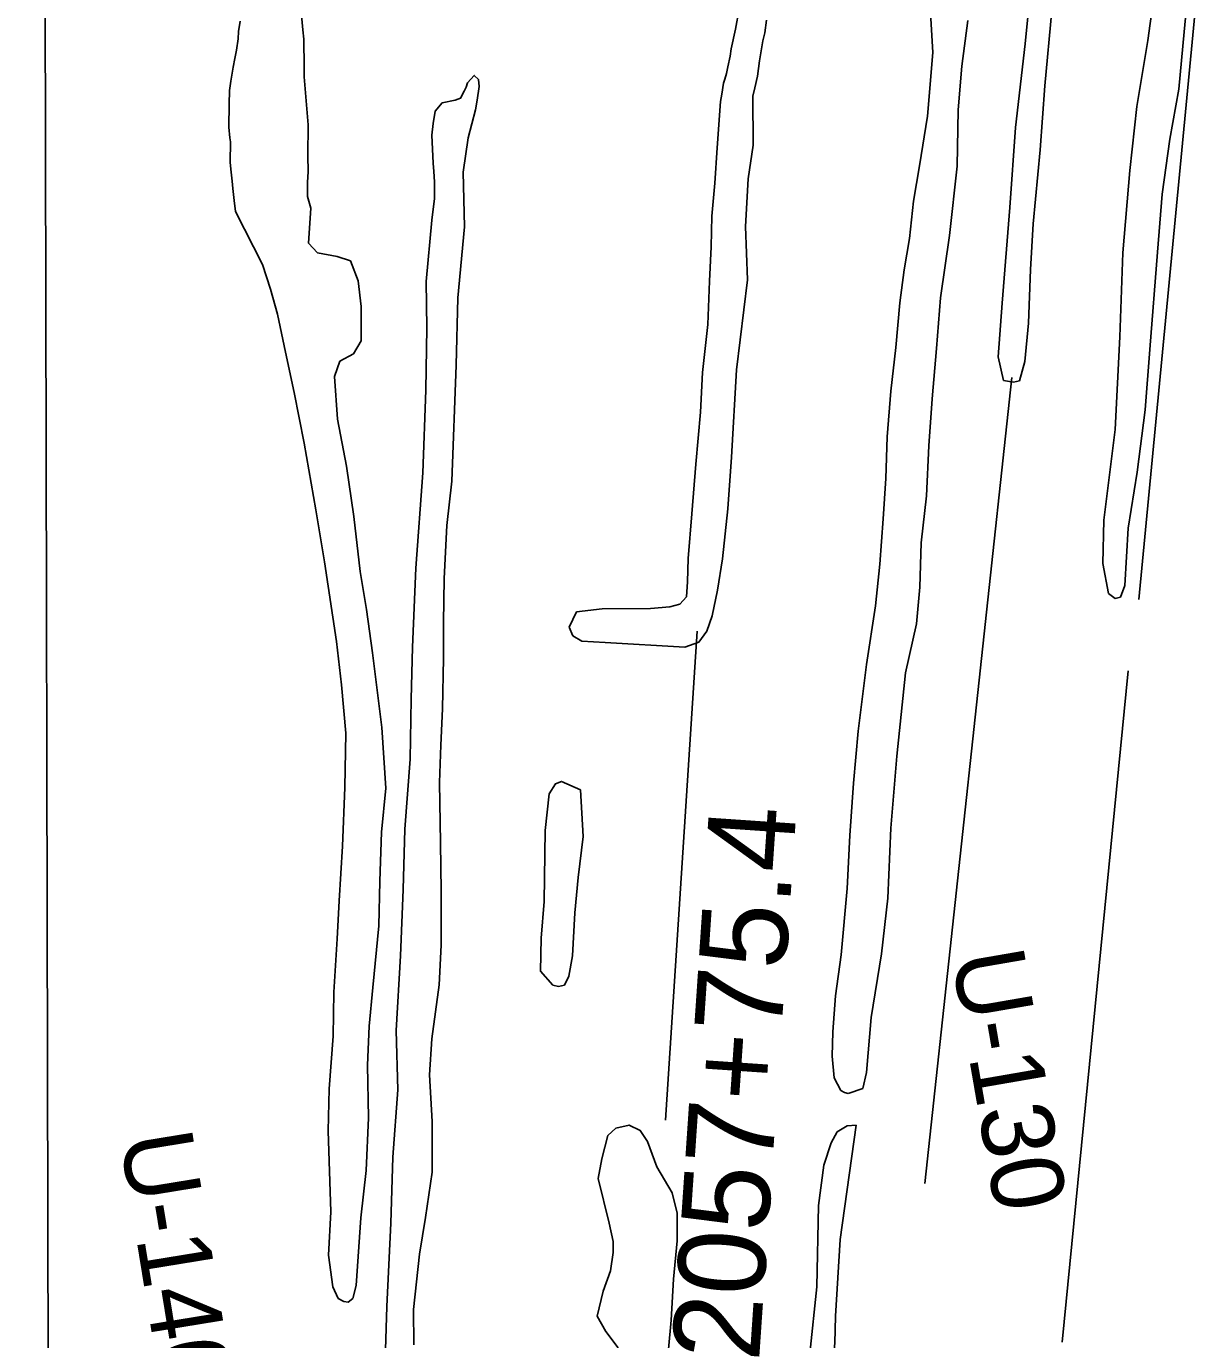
# Model space of a CAD drawing. Extents: x 3355677 to 3393573, y 612928 to 638357.
# Drawn here: x 3359768 to 3361105, y 625120 to 626625 of the extents above; entities that cross this region are included whole.
import ezdxf

# ---------------------------------------------------------------- set-up
doc = ezdxf.new("R2010")
doc.units = 0
for name, color, linetype in [('V-GRID-FRAM', 7, 'Continuous'), ('V-RIVR-RANG-IDEN', 7, 'Continuous'), ('V-SITE-VEGE', 7, 'Continuous'), ('V-SURV-IDEN', 7, 'Continuous'), ('V-TOPO-SHOR', 7, 'Continuous')]:
    doc.layers.add(name, color=color, linetype=linetype)

msp = doc.modelspace()

# ---------------------------------------------------------------- linework, layer by layer
at = {"layer": 'V-GRID-FRAM'}
msp.add_lwpolyline([(3359767.9, 636495.9), (3391341.6, 636578.5), (3391397.2, 618394.8), (3359807.6, 618312.1), (3359767.9, 636495.9)], dxfattribs=at)
at = {"layer": 'V-SITE-VEGE'}
for p, q in [((3361102.1, 626698.5), (3361094.6, 626618.8)), ((3360912.3, 626605.1), (3360920.5, 626686.1)), ((3361052.7, 626608.9), (3361063, 626680.9)), ((3360081.1, 626663.3), (3360084.9, 626621.1)), ((3360580.5, 626622), (3360584.7, 626644.8)), ((3360806.5, 626595.3), (3360803.4, 626647.2)), ((3360011.2, 626619.3), (3360012.9, 626631.1)), ((3360616.1, 626632.2), (3360613.9, 626617.7)), ((3360846.6, 626632.1), (3360839.8, 626579.7)), ((3360943, 626643.6), (3360934.8, 626556.9)), ((3360010.7, 626611), (3360011.2, 626619.3)), ((3360084.9, 626621.1), (3360086, 626610.4)), ((3360575.5, 626599.6), (3360580.5, 626622)), ((3360613.9, 626617.7), (3360611.9, 626608.6)), ((3361094.6, 626618.8), (3361088.5, 626553.2)), ((3360008.6, 626598), (3360010.7, 626611)), ((3360086, 626610.4), (3360086.3, 626578.1)), ((3360611.9, 626608.6), (3360609.3, 626594.9)), ((3360901.4, 626509.3), (3360912.3, 626605.1)), ((3361040.4, 626533.5), (3361052.7, 626608.9)), ((3360004.8, 626578.4), (3360006.9, 626588.6)), ((3360006.9, 626588.6), (3360008.6, 626598)), ((3360571.7, 626578.8), (3360574.2, 626591)), ((3360574.2, 626591), (3360575.5, 626599.6)), ((3360608, 626585.8), (3360605.8, 626568.1)), ((3360609.3, 626594.9), (3360608, 626585.8)), ((3360800.4, 626522.3), (3360806.5, 626595.3)), ((3360002.2, 626562.6), (3360004.8, 626578.4)), ((3360086.3, 626578.1), (3360086.2, 626567.5)), ((3360568.4, 626564.7), (3360570, 626571.3)), ((3360570, 626571.3), (3360571.7, 626578.8)), ((3360839.8, 626579.7), (3360835.7, 626529.4)), ((3360000.9, 626551.6), (3360002.2, 626562.6)), ((3360086.2, 626567.5), (3360091, 626512.3)), ((3360564.6, 626547.4), (3360566.7, 626560)), ((3360566.7, 626560), (3360568.4, 626564.7)), ((3360602.5, 626554.8), (3360600.4, 626545.4)), ((3360605.8, 626568.1), (3360602.5, 626554.8)), ((3360934.8, 626556.9), (3360929.4, 626483.6)), ((3360000.3, 626535.9), (3360000.9, 626551.6)), ((3360563.3, 626539.1), (3360564.6, 626547.4)), ((3360600.4, 626545.4), (3360600.6, 626489.1)), ((3361088.5, 626553.2), (3361078.2, 626495.9)), ((3360000, 626509.9), (3360000.3, 626535.9)), ((3360559.3, 626486.2), (3360563.3, 626539.1)), ((3360835.7, 626529.4), (3360834.5, 626465.1)), ((3361032.2, 626460.1), (3361040.4, 626533.5)), ((3360001, 626497.3), (3360000, 626509.9)), ((3360091, 626512.3), (3360090.6, 626477.2)), ((3360791.4, 626465.5), (3360800.4, 626522.3)), ((3360894.7, 626417.8), (3360901.4, 626509.3)), ((3360001.8, 626492.9), (3360001, 626497.3)), ((3361078.2, 626495.9), (3361069.3, 626433)), ((3360001.5, 626469.7), (3360001.8, 626492.9)), ((3360556.6, 626445.5), (3360559.3, 626486.2)), ((3360600.6, 626489.1), (3360595.1, 626450.5)), ((3360929.4, 626483.6), (3360921.3, 626399)), ((3360002.2, 626461.4), (3360001.5, 626469.7)), ((3360090.6, 626477.2), (3360090.8, 626458.7)), ((3360784.5, 626424.8), (3360791.4, 626465.5)), ((3360834.5, 626465.1), (3360825.6, 626385.5)), ((3360003.6, 626448), (3360002.2, 626461.4)), ((3360090.8, 626458.7), (3360090.2, 626446.5)), ((3360595.1, 626450.5), (3360591.8, 626395.8)), ((3361024.1, 626365.8), (3361032.2, 626460.1)), ((3360004.6, 626439.3), (3360003.6, 626448)), ((3360006, 626425.5), (3360004.6, 626439.3)), ((3360090.2, 626446.5), (3360090, 626430.4)), ((3360553.2, 626407.6), (3360556.6, 626445.5)), ((3360007.6, 626413), (3360006, 626425.5)), ((3360090, 626430.4), (3360093.8, 626416.9)), ((3360779.8, 626382), (3360784.5, 626424.8)), ((3361069.3, 626433), (3361063.9, 626366.6)), ((3360038.6, 626352.2), (3360007.6, 626413)), ((3360093.8, 626416.9), (3360091.1, 626376.8)), ((3360552.6, 626372.5), (3360553.2, 626407.6)), ((3360885.9, 626308.1), (3360894.7, 626417.8)), ((3360591.8, 626395.8), (3360594.1, 626334.8)), ((3360921.3, 626399), (3360918.6, 626346.6)), ((3360091.1, 626376.8), (3360101.6, 626365.7)), ((3360773.5, 626346.2), (3360779.8, 626382)), ((3360825.6, 626385.5), (3360815.4, 626314.2)), ((3360101.6, 626365.7), (3360124.1, 626361.5)), ((3360124.1, 626361.5), (3360139.5, 626356.6)), ((3360550.6, 626333.3), (3360552.6, 626372.5)), ((3361020.8, 626269.4), (3361024.1, 626365.8)), ((3361063.9, 626366.6), (3361055.1, 626254.8)), ((3360047.8, 626324.1), (3360038.6, 626352.2)), ((3360139.5, 626356.6), (3360148, 626333.5)), ((3360768.7, 626308.3), (3360773.5, 626346.2)), ((3360918.6, 626346.6), (3360916, 626285.2)), ((3360148, 626333.5), (3360151.6, 626304.1)), ((3360548.6, 626283.5), (3360550.6, 626333.3)), ((3360594.1, 626334.8), (3360581.7, 626231.7)), ((3360055.6, 626295.4), (3360047.8, 626324.1)), ((3360815.4, 626314.2), (3360810.6, 626256.2)), ((3360151.6, 626304.1), (3360151.7, 626264.8)), ((3360764, 626257.1), (3360768.7, 626308.3)), ((3360881.2, 626246.6), (3360885.9, 626308.1)), ((3360064.8, 626251.9), (3360055.6, 626295.4)), ((3360916, 626285.2), (3360912, 626241.1)), ((3360542.5, 626228.7), (3360548.6, 626283.5)), ((3361015.6, 626163.2), (3361020.8, 626269.4)), ((3360151.7, 626264.8), (3360142.6, 626250.1)), ((3360758.5, 626207.3), (3360764, 626257.1)), ((3360810.6, 626256.2), (3360805.9, 626198.2)), ((3361055.1, 626254.8), (3361049.7, 626185.6)), ((3360074.7, 626205.7), (3360064.8, 626251.9)), ((3360127.2, 626241.6), (3360121, 626224)), ((3360142.6, 626250.1), (3360127.2, 626241.6)), ((3360887.6, 626219.4), (3360881.2, 626246.6)), ((3360912, 626241.1), (3360905.7, 626218.8)), ((3360121, 626224), (3360124.6, 626175)), ((3360540.5, 626183.1), (3360542.5, 626228.7)), ((3360581.7, 626231.7), (3360575.7, 626131.4)), ((3360898.8, 626217.4), (3360887.6, 626219.4)), ((3360905.7, 626218.8), (3360898.8, 626217.4)), ((3360086.1, 626147.5), (3360074.7, 626205.7)), ((3360754.4, 626154.7), (3360758.5, 626207.3)), ((3360805.9, 626198.2), (3360801.9, 626144.4)), ((3360535, 626123.5), (3360540.5, 626183.1)), ((3361049.7, 626185.6), (3361040.8, 626114.4)), ((3360124.6, 626175), (3360134.6, 626121)), ((3361002.6, 626059.1), (3361015.6, 626163.2)), ((3360752.5, 626107), (3360754.4, 626154.7)), ((3360099.7, 626071.1), (3360086.1, 626147.5)), ((3360801.9, 626144.4), (3360799.2, 626087.2)), ((3360134.6, 626121), (3360143.2, 626063.5)), ((3360530.3, 626066.7), (3360535, 626123.5)), ((3360575.7, 626131.4), (3360571.6, 626072.4)), ((3360749.8, 626060.7), (3360752.5, 626107)), ((3361040.8, 626114.4), (3361030.5, 626050.1)), ((3360799.2, 626087.2), (3360793.1, 626033.4)), ((3360109.7, 626011.5), (3360099.7, 626071.1)), ((3360143.2, 626063.5), (3360150.4, 626000.4)), ((3360526.2, 626015.5), (3360530.3, 626066.7)), ((3360571.6, 626072.4), (3360565.5, 626014.9)), ((3360745.7, 626008.8), (3360749.8, 626060.7)), ((3361001.3, 626009.5), (3361002.6, 626059.1)), ((3361030.5, 626050.1), (3361026.5, 625984.4)), ((3360793.1, 626033.4), (3360791.8, 625982.4)), ((3360525.6, 625988.8), (3360526.2, 626015.5)), ((3360565.5, 626014.9), (3360560, 625979.1)), ((3360123.2, 625920.4), (3360109.7, 626011.5)), ((3360150.4, 626000.4), (3360157.5, 625956.9)), ((3360741, 625961.1), (3360745.7, 626008.8)), ((3361007.7, 625975.3), (3361001.3, 626009.5)), ((3360524.2, 625971.3), (3360525.6, 625988.8)), ((3361026.5, 625984.4), (3361021.7, 625971.1)), ((3360516.6, 625962.9), (3360524.2, 625971.3)), ((3360560, 625979.1), (3360553.8, 625949.6)), ((3360791.8, 625982.4), (3360787.8, 625940.4)), ((3361015.4, 625969.7), (3361007.7, 625975.3)), ((3361021.7, 625971.1), (3361015.4, 625969.7)), ((3360157.5, 625956.9), (3360164.6, 625907.2)), ((3360389.7, 625936.6), (3360398.1, 625954.1)), ((3360398.1, 625954.1), (3360427.5, 625957.7)), ((3360427.5, 625957.7), (3360482.9, 625957.9)), ((3360482.9, 625957.9), (3360505.3, 625960)), ((3360505.3, 625960), (3360516.6, 625962.9)), ((3360730.6, 625893.7), (3360741, 625961.1)), ((3360553.8, 625949.6), (3360547.5, 625932.1)), ((3360787.8, 625940.4), (3360775.4, 625884.5)), ((3360393.9, 625926.8), (3360389.7, 625936.6)), ((3360404.5, 625920.5), (3360393.9, 625926.8)), ((3360547.5, 625932.1), (3360538.4, 625919.4)), ((3360129, 625870.6), (3360123.2, 625920.4)), ((3360164.6, 625907.2), (3360175.4, 625821.6)), ((3360431.1, 625919.1), (3360404.5, 625920.5)), ((3360522.3, 625913.8), (3360431.1, 625919.1)), ((3360538.4, 625919.4), (3360522.3, 625913.8)), ((3360721, 625817.3), (3360730.6, 625893.7)), ((3360775.4, 625884.5), (3360765.1, 625788.8)), ((3360134.1, 625815.2), (3360129, 625870.6)), ((3360175.4, 625821.6), (3360179.8, 625752.2)), ((3360715.6, 625757.7), (3360721, 625817.3)), ((3360132.8, 625752.8), (3360134.1, 625815.2)), ((3360765.1, 625788.8), (3360758.4, 625706.4)), ((3360711.6, 625698), (3360715.6, 625757.7)), ((3360130.2, 625685.5), (3360132.8, 625752.8)), ((3360179.8, 625752.2), (3360175, 625701.7)), ((3360175, 625701.7), (3360173.1, 625645.6)), ((3360708.2, 625637), (3360711.6, 625698)), ((3360758.4, 625706.4), (3360755.1, 625626)), ((3360126.2, 625623), (3360130.2, 625685.5)), ((3360173.1, 625645.6), (3360171.8, 625594.4)), ((3360701.4, 625561.2), (3360708.2, 625637)), ((3360124.2, 625579.5), (3360126.2, 625623)), ((3360755.1, 625626), (3360747.6, 625562.4)), ((3360171.8, 625594.4), (3360165, 625523.6)), ((3360120.2, 625518.5), (3360124.2, 625579.5)), ((3360695.2, 625514.2), (3360701.4, 625561.2)), ((3360747.6, 625562.4), (3360736, 625489.1)), ((3360119.6, 625468), (3360120.2, 625518.5)), ((3360165, 625523.6), (3360160.9, 625479.4)), ((3360691.8, 625472.8), (3360695.2, 625514.2)), ((3360736, 625489.1), (3360730.5, 625426.2)), ((3360160.9, 625479.4), (3360159, 625434.5)), ((3360691.2, 625444.8), (3360691.8, 625472.8)), ((3360114.9, 625407.7), (3360119.6, 625468)), ((3360693.4, 625420.3), (3360691.2, 625444.8)), ((3360159, 625434.5), (3360159.8, 625374.2)), ((3360730.5, 625426.2), (3360726.4, 625408)), ((3360701.2, 625405.5), (3360693.4, 625420.3)), ((3360113.6, 625359.3), (3360114.9, 625407.7)), ((3360705.4, 625403.5), (3360701.2, 625405.5)), ((3360709.6, 625402.1), (3360705.4, 625403.5)), ((3360726.4, 625408), (3360709.6, 625402.1)), ((3360159.8, 625374.2), (3360157.2, 625313.8)), ((3360116.7, 625266.7), (3360113.6, 625359.3)), ((3360157.2, 625313.8), (3360151, 625259.8)), ((3360114, 625216.9), (3360116.7, 625266.7)), ((3360151, 625259.8), (3360145.7, 625182)), ((3360119, 625180.5), (3360114, 625216.9)), ((3360125.4, 625167.2), (3360119, 625180.5)), ((3360145.7, 625182), (3360142.2, 625167.2)), ((3360131.7, 625163.7), (3360125.4, 625167.2)), ((3360136.6, 625163), (3360131.7, 625163.7)), ((3360142.2, 625167.2), (3360136.6, 625163))]:
    msp.add_line(p, q, dxfattribs=at)
for points in [[(3360179.5, 625108.4), (3360180.8, 625158.2), (3360185.4, 625253.6), (3360188, 625329.4), (3360193.4, 625406.5), (3360191.8, 625474.5), (3360196.5, 625560.1), (3360199.8, 625635.9), (3360201.7, 625705.3), (3360207.8, 625785.3), (3360209, 625854), (3360210.2, 625913.6), (3360214.2, 626004.1), (3360222.3, 626113.5), (3360225.5, 626208.2), (3360226.7, 626279.7), (3360225.9, 626333), (3360232.7, 626403.2), (3360235.4, 626427.8), (3360235.6, 626447.2), (3360234.8, 626459), (3360234, 626468.4), (3360232.5, 626500.6), (3360234, 626514), (3360236.4, 626528.1), (3360244.2, 626537.6), (3360259.2, 626540.7), (3360265.4, 626543.1), (3360269.4, 626550.9), (3360271.7, 626555.6), (3360273.3, 626560.4), (3360281.1, 626569), (3360285.9, 626564.3), (3360286.6, 626556.4), (3360284.3, 626540.7), (3360282.7, 626529.7), (3360274.1, 626497.5), (3360268.3, 626458), (3360269.9, 626395.6), (3360262.4, 626314.2), (3360260.5, 626237.1), (3360255.3, 626103.8), (3360249.8, 626053.3), (3360246.5, 625992.3), (3360245.9, 625941.8), (3360246, 625901.1), (3360244.8, 625842.9), (3360242.8, 625801.5), (3360241.5, 625758.7), (3360242.4, 625689.3), (3360243.3, 625633.9), (3360243.4, 625572.2), (3360240.8, 625526.6), (3360232.5, 625464.8), (3360229.8, 625423.4), (3360232.8, 625370.2), (3360233, 625312), (3360225.4, 625260), (3360218.5, 625217.9), (3360211.7, 625154.8), (3360211.8, 625114.1)], [(3360446, 625110.6), (3360431.9, 625129.5), (3360422.1, 625147), (3360429, 625175.7), (3360437.4, 625198.9), (3360440.1, 625220), (3360440.1, 625232.6), (3360435.8, 625253.6), (3360423, 625304.8), (3360427.2, 625327.2), (3360434.1, 625353.9), (3360443.2, 625362.3), (3360458.6, 625365.9), (3360471.3, 625359.6), (3360479.7, 625347), (3360490.3, 625318.3), (3360507.9, 625288.2), (3360513.6, 625265), (3360513.7, 625233.5), (3360509.6, 625189.3), (3360506.9, 625142.3), (3360503.5, 625109.3)]]:
    msp.add_lwpolyline(points, dxfattribs=at)
for points in [[(3360402.8, 625750.1), (3360405.8, 625696.8), (3360400.3, 625649.8), (3360396.2, 625609.1), (3360393.6, 625560), (3360389.4, 625536.8), (3360384.5, 625526.3), (3360377.5, 625524.9), (3360371.2, 625526.2), (3360357.1, 625542.3), (3360357.7, 625580.2), (3360361.1, 625622.3), (3360362.3, 625703.6), (3360367.1, 625745.7), (3360374.1, 625757), (3360381.1, 625759.8)], [(3360718.8, 625365.9), (3360700.2, 625234.7), (3360694.9, 625147), (3360694.3, 625116.2), (3360692.2, 625097.9), (3360687.3, 625084.6), (3360680.3, 625078.3), (3360675.4, 625081.1), (3360665.5, 625104.2), (3360673.7, 625180.6), (3360675.6, 625273.9), (3360681.8, 625320.2), (3360690.1, 625345.5), (3360697.1, 625358.1), (3360708.3, 625365.2)]]:
    msp.add_lwpolyline(points, close=True, dxfattribs=at)
at = {"layer": 'V-TOPO-SHOR'}
for p, q in [((3360897.2, 626222.8), (3360797.2, 625298.9)), ((3360500.3, 625371.6), (3360536.7, 625932)), ((3361030.4, 625886.5), (3360954.7, 625117.1))]:
    msp.add_line(p, q, dxfattribs=at)
msp.add_lwpolyline([(3361160.7, 627119.4), (3361112.2, 626695.3), (3361042.6, 625968.3)], dxfattribs=at)

# ---------------------------------------------------------------- texts
at = {"layer": 'V-RIVR-RANG-IDEN'}
for s, rotation, p in [('U-130', 279.8223, (3360827.7, 625560.1)), ('U-140', 279.2843, (3359874.9, 625352.3))]:
    msp.add_text(s, height=83, rotation=rotation, dxfattribs=at).set_placement(p)
at = {"layer": 'V-SURV-IDEN'}
msp.add_text('2057+75.4', height=100, rotation=86.1175, dxfattribs=at).set_placement((3360607.3, 625094))

doc.saveas('drawing.dxf')
